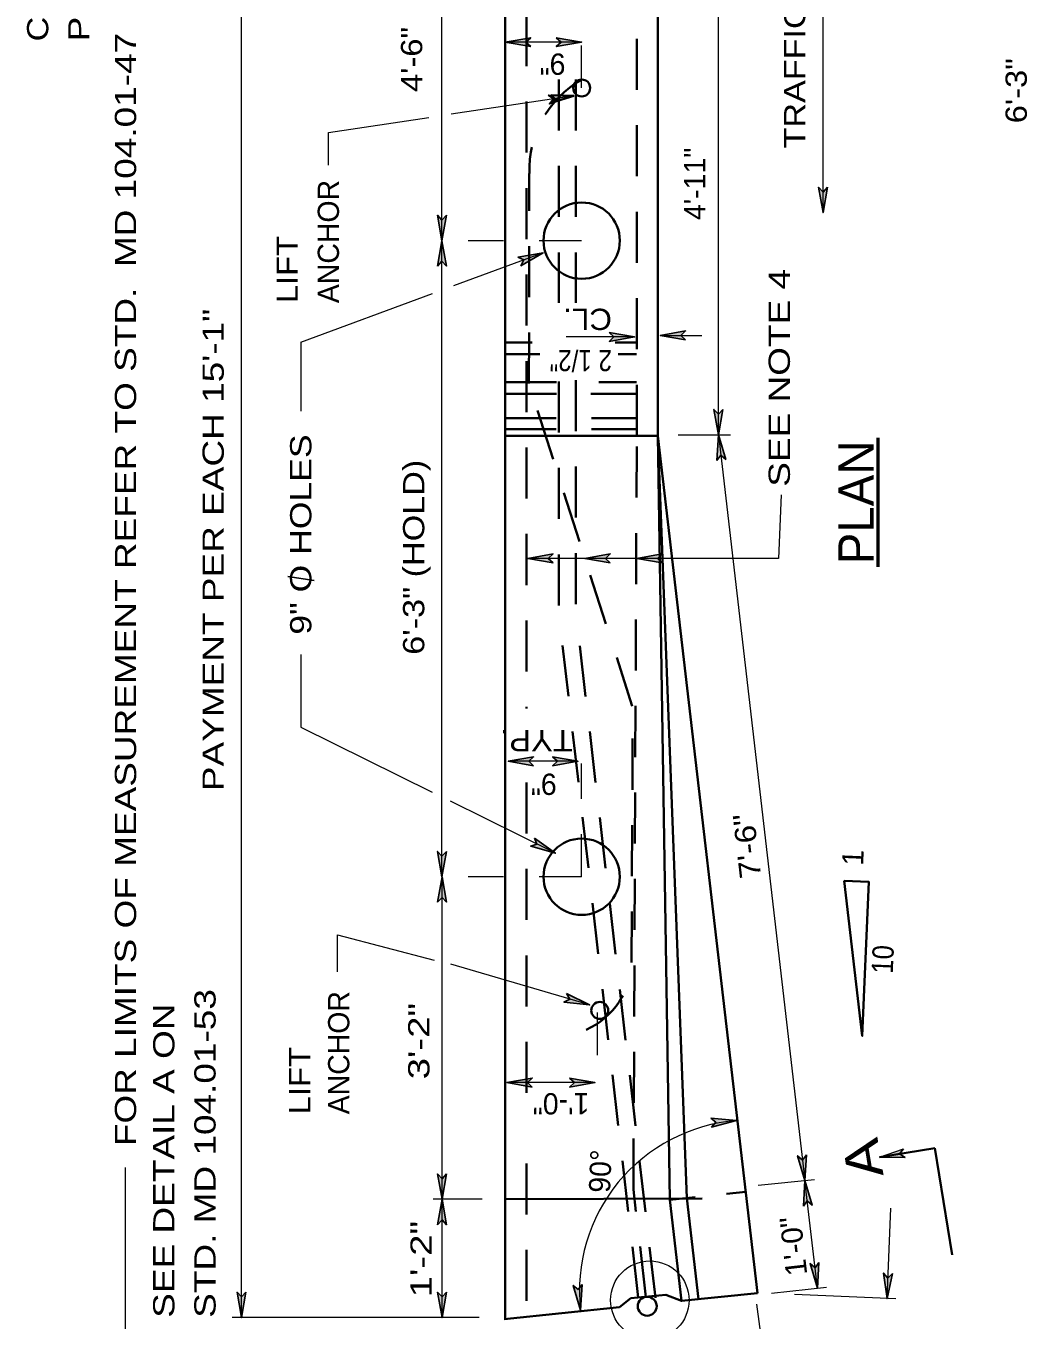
# Model space of a CAD drawing. Extents: x 12.6 to 19.5, y 6.1 to 16.3.
# Drawn here: x 12.689 to 15.514, y 8.696 to 12.348 of the extents above; entities that cross this region are included whole.
import ezdxf
from ezdxf.enums import TextEntityAlignment as Align

# ---------------------------------------------------------------- set-up
doc = ezdxf.new("R2010")
doc.units = 0
doc.header["$LTSCALE"] = 0.024
doc.linetypes.add('DOT_DASHED', pattern=[7.7, 5, -1.2, 0.3, -1.2])
doc.linetypes.add('LONG_DASHED', pattern=[7.5, 6, -1.5])
for name, color, linetype, lineweight in [('1', 7, 'Continuous', 35), ('10', 7, 'Continuous', 25), ('12', 7, 'Continuous', 53)]:
    doc.layers.add(name, color=color, linetype=linetype, lineweight=lineweight)

msp = doc.modelspace()

# ---------------------------------------------------------------- hatches: boundary and pattern name
at = {"layer": '10'}
for points in [[(14.1137, 12.2895), (14.0422, 12.3021), (14.1137, 12.3147), (14.1002, 12.3021)], [(14.186, 12.3147), (14.2575, 12.3021), (14.186, 12.2895), (14.1995, 12.3021)], [(14.1627, 12.1529), (14.2353, 12.1511), (14.1665, 12.128), (14.1779, 12.1425)], [(14.9513, 11.8926), (14.9387, 11.8211), (14.9261, 11.8926), (14.9387, 11.8791)], [(13.8761, 11.8135), (13.8635, 11.742), (13.8509, 11.8135), (13.8635, 11.8)], [(13.8509, 11.6705), (13.8635, 11.742), (13.8761, 11.6705), (13.8635, 11.684)], [(14.0774, 11.6951), (14.1488, 11.708), (14.0861, 11.6714), (14.0944, 11.6879)], [(14.3352, 11.483), (14.4067, 11.4704), (14.3352, 11.4578), (14.3487, 11.4704)], [(14.5506, 11.4621), (14.4791, 11.4747), (14.5506, 11.4873), (14.5371, 11.4747)], [(14.6558, 11.266), (14.6432, 11.1945), (14.6306, 11.266), (14.6432, 11.2525)], [(14.6389, 11.122), (14.6432, 11.1945), (14.664, 11.1249), (14.6499, 11.1369)], [(14.1768, 10.8328), (14.1053, 10.8454), (14.1768, 10.858), (14.1633, 10.8454)], [(14.3383, 10.8328), (14.2668, 10.8454), (14.3383, 10.858), (14.3248, 10.8454)], [(14.4846, 10.8328), (14.4131, 10.8454), (14.4846, 10.858), (14.4711, 10.8454)], [(14.122, 10.2604), (14.0505, 10.273), (14.122, 10.2856), (14.1085, 10.273)], [(14.1755, 10.2856), (14.247, 10.273), (14.1755, 10.2604), (14.189, 10.273)], [(14.1249, 10.0566), (14.1834, 10.0136), (14.1137, 10.034), (14.1314, 10.0393)], [(13.8761, 10.0187), (13.8635, 9.9472), (13.8509, 10.0187), (13.8635, 10.0052)], [(13.851, 9.8757), (13.8636, 9.9472), (13.8762, 9.8757), (13.8636, 9.8892)], [(14.2146, 9.6181), (14.2797, 9.5859), (14.2075, 9.5939), (14.224, 9.6022)], [(14.1182, 9.3539), (14.0467, 9.3665), (14.1182, 9.3791), (14.1047, 9.3665)], [(14.2235, 9.3791), (14.295, 9.3665), (14.2235, 9.3539), (14.237, 9.3665)], [(14.622, 9.266), (14.6943, 9.2592), (14.624, 9.2409), (14.6364, 9.2546)], [(15.1701, 9.155), (15.0975, 9.1559), (15.166, 9.1799), (15.1547, 9.1652)], [(14.8917, 9.1629), (14.8874, 9.0904), (14.8666, 9.16), (14.8807, 9.148)], [(13.8762, 9.1087), (13.8636, 9.0372), (13.851, 9.1087), (13.8636, 9.0952)], [(14.8831, 9.0179), (14.8874, 9.0904), (14.9082, 9.0208), (14.8941, 9.0328)], [(13.851, 8.9657), (13.8636, 9.0372), (13.8762, 8.9657), (13.8636, 8.9792)], [(14.927, 8.8588), (14.9227, 8.7863), (14.9019, 8.8559), (14.916, 8.8439)], [(15.1348, 8.8282), (15.1192, 8.7573), (15.1096, 8.8293), (15.1216, 8.8152)], [(13.3104, 8.7752), (13.2978, 8.7037), (13.2852, 8.7752), (13.2978, 8.7617)], [(13.8762, 8.7752), (13.8636, 8.7037), (13.851, 8.7752), (13.8636, 8.7617)], [(14.2587, 8.7973), (14.2543, 8.7248), (14.2337, 8.7944), (14.2477, 8.7824)]]:
    msp.add_hatch(color=256, dxfattribs=at).paths.add_polyline_path(points)

# ---------------------------------------------------------------- linework, layer by layer
at = {"layer": '1', "linetype": 'LONG_DASHED'}
for p, q in [((14.1021, 12.8664), (14.1021, 10.4224)), ((14.1928, 12.1968), (14.1928, 11.5662)), ((14.2415, 12.1968), (14.2415, 11.5662)), ((14.1087, 11.3386), (14.1099, 11.9313)), ((14.0429, 11.4546), (14.1177, 11.4546)), ((14.4123, 11.4546), (14.3519, 11.4546)), ((14.0429, 11.4222), (14.1399, 11.4222)), ((14.4123, 11.4222), (14.3604, 11.4222)), ((14.0429, 11.3427), (14.1927, 11.3427)), ((14.4003, 10.4286), (14.1087, 11.3386)), ((14.1928, 11.345), (14.1928, 10.6914)), ((14.2415, 11.3485), (14.2415, 10.6912)), ((14.4123, 11.3427), (14.3059, 11.3427)), ((14.0429, 11.3102), (14.2012, 11.3102)), ((14.4123, 11.3102), (14.2838, 11.3102)), ((14.0412, 11.241), (14.4106, 11.241)), ((14.0412, 11.2102), (14.4107, 11.2102)), ((14.4173, 8.7603), (14.1928, 10.6914)), ((14.466, 8.7595), (14.2415, 10.6912)), ((14.398, 9.705), (14.402, 10.4323)), ((14.1021, 9.3376), (14.1021, 10.2412)), ((14.1021, 8.7507), (14.1021, 9.2374))]:
    msp.add_line(p, q, dxfattribs=at)
at = {"layer": '1'}
for p, q in [((14.1714, 12.1521), (14.2353, 12.1511)), ((14.1714, 12.1521), (14.1808, 12.1429)), ((14.1746, 12.1314), (14.2353, 12.1511)), ((14.1746, 12.1314), (14.1808, 12.1429)), ((14.7537, 8.7728), (14.4728, 11.1918)), ((14.5064, 9.036), (14.4728, 11.1918)), ((14.554, 9.0408), (14.4728, 11.1918)), ((14.7207, 9.058), (14.6664, 9.0525)), ((14.5975, 9.0392), (14.0422, 9.0379)), ((14.5064, 9.036), (14.578, 9.0433)), ((14.5872, 8.7556), (14.554, 9.0408)), ((14.4948, 8.7681), (14.3964, 8.7579)), ((14.7537, 8.7728), (14.5395, 8.7507)), ((14.0385, 8.6991), (14.364, 8.7327)), ((14.3964, 8.7579), (14.364, 8.7327))]:
    msp.add_line(p, q, dxfattribs=at)
for points in [[(14.0422, 13.0162), (14.0422, 11.1916), (14.4729, 11.1916), (14.4729, 12.6034)], [(14.0422, 11.1916), (14.0422, 9.0379), (14.0422, 8.7029)], [(14.4948, 8.7681), (14.5395, 8.7507), (14.5064, 9.036)]]:
    msp.add_lwpolyline(points, dxfattribs=at)
at = {"layer": '1', "linetype": 'LONG_DASHED'}
for points in [[(14.4131, 11.1916), (14.4131, 12.6034), (14.3534, 12.8719)], [(14.4391, 8.7607), (14.4036, 9.0652), (14.413, 11.1943)]]:
    msp.add_lwpolyline(points, dxfattribs=at)
at = {"layer": '1'}
for centre, radius in [((14.25762, 12.1728), 0.02393), ((14.25762, 11.74206), 0.10769), ((14.25762, 9.94731), 0.10769), ((14.3085, 9.57006), 0.02393), ((14.44257, 8.73553), 0.02674)]:
    msp.add_circle(centre, radius, dxfattribs=at)
at = {"layer": '1', "linetype": 'LONG_DASHED'}
msp.add_arc((14.40409, 11.94159), 0.29419, 119.85944, 181.98584, dxfattribs=at)
msp.add_ellipse((14.18968, 9.69707), major_axis=(0.19051, 0.08479), ratio=0.952525, start_param=4.712389, end_param=5.9027397, dxfattribs=at)
at = {"layer": '10', "lineweight": 13}
for p, q in [((14.9387, 11.8211), (14.9387, 13.1462)), ((13.2978, 8.7037), (13.2978, 13.0311)), ((14.2575, 12.3021), (14.0422, 12.3021)), ((14.2353, 12.1511), (13.8898, 12.0991)), ((13.5428, 12.0468), (13.8266, 12.0896)), ((13.5428, 11.9551), (13.5428, 12.0468)), ((14.1488, 11.708), (13.8959, 11.6148)), ((13.4649, 11.456), (13.8366, 11.5929)), ((14.4067, 11.4704), (14.2138, 11.4704)), ((14.4791, 11.4747), (14.597, 11.4747)), ((13.4649, 11.456), (13.4649, 11.2607)), ((14.5303, 11.1945), (14.6772, 11.1945)), ((14.6432, 11.1945), (14.8874, 9.0904)), ((14.8201, 11.025), (14.8125, 10.8454)), ((14.2668, 10.8454), (14.1053, 10.8454)), ((13.4649, 10.5746), (13.4649, 10.3698)), ((13.4649, 10.3698), (13.8354, 10.1861)), ((14.247, 10.273), (14.0505, 10.273)), ((14.1834, 10.0136), (13.8873, 10.1603)), ((13.5687, 9.679), (13.5687, 9.7833)), ((13.5687, 9.7833), (13.8414, 9.7118)), ((14.2797, 9.5859), (13.8882, 9.7005)), ((14.295, 9.3665), (14.0467, 9.3665)), ((15.0975, 9.1559), (15.166, 9.1799)), ((15.0975, 9.1559), (15.1701, 9.155)), ((12.9705, 8.2335), (12.9705, 9.1269)), ((14.7555, 9.0768), (14.9146, 9.0932)), ((14.9227, 8.7863), (14.8874, 9.0904)), ((13.9765, 9.0372), (13.8386, 9.0372)), ((15.1192, 8.7573), (15.13, 9.0125)), ((14.793, 8.7729), (14.9484, 8.7889)), ((15.1441, 8.7562), (14.8584, 8.7684)), ((14.7507, 8.7412), (14.8253, 8.1913)), ((13.8537, 8.7037), (13.2719, 8.7037)), ((13.968, 8.7037), (13.8537, 8.7037))]:
    msp.add_line(p, q, dxfattribs=at)
at = {"layer": '10'}
for p, q in [((14.0422, 12.3021), (14.1137, 12.3147)), ((14.2575, 12.3021), (14.186, 12.3147)), ((14.0422, 12.3021), (14.1137, 12.2895)), ((14.2575, 12.3021), (14.186, 12.2895)), ((14.2353, 12.1511), (14.1627, 12.1529)), ((14.2353, 12.1511), (14.1665, 12.128)), ((14.9387, 11.8211), (14.9261, 11.8926)), ((14.9387, 11.8211), (14.9513, 11.8926)), ((13.8635, 11.742), (13.8509, 11.8135)), ((13.8635, 11.742), (13.8761, 11.8135)), ((13.8635, 11.742), (13.8509, 11.6705)), ((13.8635, 11.742), (13.8761, 11.6705)), ((14.1488, 11.708), (14.0774, 11.6951)), ((14.1488, 11.708), (14.0861, 11.6714)), ((14.4067, 11.4704), (14.3352, 11.483)), ((14.4067, 11.4704), (14.3352, 11.4578)), ((14.4791, 11.4747), (14.5506, 11.4873)), ((14.4791, 11.4747), (14.5506, 11.4621)), ((14.6432, 11.1945), (14.6306, 11.266)), ((14.6432, 11.1945), (14.6558, 11.266)), ((14.6432, 11.1945), (14.6389, 11.122)), ((14.6432, 11.1945), (14.664, 11.1249)), ((14.1053, 10.8454), (14.1768, 10.858)), ((14.1053, 10.8454), (14.1768, 10.8328)), ((14.2668, 10.8454), (14.3383, 10.858)), ((14.2668, 10.8454), (14.3383, 10.8328)), ((14.4131, 10.8454), (14.4846, 10.858)), ((14.4131, 10.8454), (14.4846, 10.8328)), ((13.503, 10.7836), (13.4286, 10.7944)), ((14.0505, 10.273), (14.122, 10.2856)), ((14.0505, 10.273), (14.122, 10.2604)), ((14.247, 10.273), (14.1755, 10.2856)), ((14.247, 10.273), (14.1755, 10.2604)), ((14.1834, 10.0136), (14.1249, 10.0566)), ((13.8635, 9.9472), (13.8509, 10.0187)), ((13.8635, 9.9472), (13.8761, 10.0187)), ((14.1834, 10.0136), (14.1137, 10.034)), ((13.8636, 9.9472), (13.851, 9.8757)), ((13.8636, 9.9472), (13.8762, 9.8757)), ((14.2797, 9.5859), (14.2146, 9.6181)), ((14.2797, 9.5859), (14.2075, 9.5939)), ((14.0467, 9.3665), (14.1182, 9.3791)), ((14.0467, 9.3665), (14.1182, 9.3539)), ((14.295, 9.3665), (14.2235, 9.3791)), ((14.295, 9.3665), (14.2235, 9.3539)), ((14.6943, 9.2592), (14.622, 9.266)), ((14.6943, 9.2592), (14.624, 9.2409)), ((14.8874, 9.0904), (14.8666, 9.16)), ((14.8874, 9.0904), (14.8917, 9.1629)), ((13.8636, 9.0372), (13.851, 9.1087)), ((13.8636, 9.0372), (13.8762, 9.1087)), ((14.8874, 9.0904), (14.8831, 9.0179)), ((14.8874, 9.0904), (14.9082, 9.0208)), ((13.8636, 9.0372), (13.851, 8.9657)), ((13.8636, 9.0372), (13.8762, 8.9657)), ((14.9227, 8.7863), (14.9019, 8.8559)), ((14.9227, 8.7863), (14.927, 8.8588)), ((15.1192, 8.7573), (15.1096, 8.8293)), ((15.1192, 8.7573), (15.1348, 8.8282)), ((13.2978, 8.7037), (13.2852, 8.7752)), ((13.2978, 8.7037), (13.3104, 8.7752)), ((13.8636, 8.7037), (13.851, 8.7752)), ((13.8636, 8.7037), (13.8762, 8.7752)), ((14.2543, 8.7248), (14.2337, 8.7944)), ((14.2543, 8.7248), (14.2587, 8.7973))]:
    msp.add_line(p, q, dxfattribs=at)
at = {"layer": '10', "linetype": 'DOT_DASHED', "lineweight": 13}
for p, q in [((14.2575, 12.1728), (14.2575, 12.3271)), ((14.2575, 11.742), (13.8385, 11.742)), ((14.2575, 9.9472), (14.2575, 10.3386)), ((14.2575, 9.9472), (13.8385, 9.9472)), ((14.3016, 9.5643), (14.3016, 9.3451))]:
    msp.add_line(p, q, dxfattribs=at)
at = {"layer": '10', "lineweight": 35}
for p, q in [((15.2543, 9.1815), (15.0975, 9.1559)), ((15.2542, 9.1818), (15.3033, 8.8809))]:
    msp.add_line(p, q, dxfattribs=at)
at = {"layer": '10', "lineweight": 13}
for points in [[(13.8635, 9.9472), (13.8635, 11.742), (13.8635, 13.0311)], [(14.6432, 11.1945), (14.6432, 12.6313), (14.6432, 13.0342)], [(14.8125, 10.8454), (14.4131, 10.8454), (14.2668, 10.8454)], [(13.8636, 8.7037), (13.8636, 9.0372), (13.8636, 9.9472)], [(15.1701, 9.155), (15.1547, 9.1652), (15.166, 9.1799)]]:
    msp.add_lwpolyline(points, dxfattribs=at)
at = {"layer": '10'}
for points in [[(14.1137, 12.2895), (14.0422, 12.3021), (14.1137, 12.3147), (14.1002, 12.3021)], [(14.186, 12.3147), (14.2575, 12.3021), (14.186, 12.2895), (14.1995, 12.3021)], [(14.1627, 12.1529), (14.2353, 12.1511), (14.1665, 12.128), (14.1779, 12.1425)], [(14.9513, 11.8926), (14.9387, 11.8211), (14.9261, 11.8926), (14.9387, 11.8791)], [(13.8761, 11.8135), (13.8635, 11.742), (13.8509, 11.8135), (13.8635, 11.8)], [(13.8509, 11.6705), (13.8635, 11.742), (13.8761, 11.6705), (13.8635, 11.684)], [(14.0774, 11.6951), (14.1488, 11.708), (14.0861, 11.6714), (14.0944, 11.6879)], [(14.3352, 11.483), (14.4067, 11.4704), (14.3352, 11.4578), (14.3487, 11.4704)], [(14.5506, 11.4621), (14.4791, 11.4747), (14.5506, 11.4873), (14.5371, 11.4747)], [(14.6558, 11.266), (14.6432, 11.1945), (14.6306, 11.266), (14.6432, 11.2525)], [(14.6389, 11.122), (14.6432, 11.1945), (14.664, 11.1249), (14.6499, 11.1369)], [(14.1768, 10.8328), (14.1053, 10.8454), (14.1768, 10.858), (14.1633, 10.8454)], [(14.3383, 10.8328), (14.2668, 10.8454), (14.3383, 10.858), (14.3248, 10.8454)], [(14.4846, 10.8328), (14.4131, 10.8454), (14.4846, 10.858), (14.4711, 10.8454)], [(14.122, 10.2604), (14.0505, 10.273), (14.122, 10.2856), (14.1085, 10.273)], [(14.1755, 10.2856), (14.247, 10.273), (14.1755, 10.2604), (14.189, 10.273)], [(14.1249, 10.0566), (14.1834, 10.0136), (14.1137, 10.034), (14.1314, 10.0393)], [(13.8761, 10.0187), (13.8635, 9.9472), (13.8509, 10.0187), (13.8635, 10.0052)], [(13.851, 9.8757), (13.8636, 9.9472), (13.8762, 9.8757), (13.8636, 9.8892)], [(14.2146, 9.6181), (14.2797, 9.5859), (14.2075, 9.5939), (14.224, 9.6022)], [(14.1182, 9.3539), (14.0467, 9.3665), (14.1182, 9.3791), (14.1047, 9.3665)], [(14.2235, 9.3791), (14.295, 9.3665), (14.2235, 9.3539), (14.237, 9.3665)], [(14.622, 9.266), (14.6943, 9.2592), (14.624, 9.2409), (14.6364, 9.2546)], [(14.8917, 9.1629), (14.8874, 9.0904), (14.8666, 9.16), (14.8807, 9.148)], [(13.8762, 9.1087), (13.8636, 9.0372), (13.851, 9.1087), (13.8636, 9.0952)], [(14.8831, 9.0179), (14.8874, 9.0904), (14.9082, 9.0208), (14.8941, 9.0328)], [(13.851, 8.9657), (13.8636, 9.0372), (13.8762, 8.9657), (13.8636, 8.9792)], [(14.927, 8.8588), (14.9227, 8.7863), (14.9019, 8.8559), (14.916, 8.8439)], [(15.1348, 8.8282), (15.1192, 8.7573), (15.1096, 8.8293), (15.1216, 8.8152)], [(13.3104, 8.7752), (13.2978, 8.7037), (13.2852, 8.7752), (13.2978, 8.7617)], [(13.8762, 8.7752), (13.8636, 8.7037), (13.851, 8.7752), (13.8636, 8.7617)], [(14.2587, 8.7973), (14.2543, 8.7248), (14.2337, 8.7944), (14.2477, 8.7824)]]:
    msp.add_lwpolyline(points, close=True, dxfattribs=at)
for points in [[(14.1137, 12.2895), (14.1002, 12.3021), (14.1137, 12.3147)], [(14.186, 12.3147), (14.1995, 12.3021), (14.186, 12.2895)], [(14.1627, 12.1529), (14.1779, 12.1425), (14.1665, 12.128)], [(14.9513, 11.8926), (14.9387, 11.8791), (14.9261, 11.8926)], [(13.8761, 11.8135), (13.8635, 11.8), (13.8509, 11.8135)], [(14.0774, 11.6951), (14.0944, 11.6879), (14.0861, 11.6714)], [(13.8509, 11.6705), (13.8635, 11.684), (13.8761, 11.6705)], [(14.3352, 11.483), (14.3487, 11.4704), (14.3352, 11.4578)], [(14.5506, 11.4621), (14.5371, 11.4747), (14.5506, 11.4873)], [(14.6558, 11.266), (14.6432, 11.2525), (14.6306, 11.266)], [(14.6389, 11.122), (14.6499, 11.1369), (14.664, 11.1249)], [(14.1768, 10.8328), (14.1633, 10.8454), (14.1768, 10.858)], [(14.3383, 10.8328), (14.3248, 10.8454), (14.3383, 10.858)], [(14.4846, 10.8328), (14.4711, 10.8454), (14.4846, 10.858)], [(14.122, 10.2604), (14.1085, 10.273), (14.122, 10.2856)], [(14.1755, 10.2856), (14.189, 10.273), (14.1755, 10.2604)], [(14.1249, 10.0566), (14.1314, 10.0393), (14.1137, 10.034)], [(13.8761, 10.0187), (13.8635, 10.0052), (13.8509, 10.0187)], [(13.851, 9.8757), (13.8636, 9.8892), (13.8762, 9.8757)], [(14.2146, 9.6181), (14.224, 9.6022), (14.2075, 9.5939)], [(14.1182, 9.3539), (14.1047, 9.3665), (14.1182, 9.3791)], [(14.2235, 9.3791), (14.237, 9.3665), (14.2235, 9.3539)], [(14.622, 9.266), (14.6364, 9.2546), (14.624, 9.2409)], [(14.8917, 9.1629), (14.8807, 9.148), (14.8666, 9.16)], [(13.8762, 9.1087), (13.8636, 9.0952), (13.851, 9.1087)], [(14.8831, 9.0179), (14.8941, 9.0328), (14.9082, 9.0208)], [(13.851, 8.9657), (13.8636, 8.9792), (13.8762, 8.9657)], [(14.927, 8.8588), (14.916, 8.8439), (14.9019, 8.8559)], [(15.1348, 8.8282), (15.1216, 8.8152), (15.1096, 8.8293)], [(13.3104, 8.7752), (13.2978, 8.7617), (13.2852, 8.7752)], [(13.8762, 8.7752), (13.8636, 8.7617), (13.851, 8.7752)], [(14.2587, 8.7973), (14.2477, 8.7824), (14.2337, 8.7944)]]:
    msp.add_lwpolyline(points, dxfattribs=at)
at = {"layer": '10', "lineweight": 35}
msp.add_lwpolyline([(14.9984, 9.9362), (15.0492, 9.4984), (15.0676, 9.9333)], close=True, dxfattribs=at)
at = {"layer": '10', "lineweight": 13}
msp.add_lwpolyline([(15.1701, 9.155), (15.0975, 9.1559), (15.166, 9.1799), (15.1547, 9.1652)], close=True, dxfattribs=at)
msp.add_circle((14.44991, 8.75269), 0.11072, dxfattribs=at)
msp.add_arc((14.73288, 8.77907), 0.48169, 94.60034, 186.46968, dxfattribs=at)
at = {"layer": '12'}
msp.add_line((15.0945, 10.8218), (15.0945, 11.1855), dxfattribs=at)

# ---------------------------------------------------------------- texts
for s, height, rotation, width, p in [('CONNECTOR LOOPS (RECEIVE THE CONNECTOR', 0.06, 90, 1.2, (12.7526, 12.3042)), ('PIN) SEE STD. MD 104.01-54 FOR DETAILS', 0.06, 90, 1.3, (12.8688, 12.3042)), ('4\'-6"', 0.06, 90, 1.15, (13.8077, 12.1614)), ('6\'-3"', 0.06, 90, 1.15, (15.5136, 12.0732)), ('LIFT', 0.06, 90, 1.15, (13.4566, 11.5657)), ('SEE NOTE 4', 0.06, 90, 1.3, (14.8451, 11.0477)), ('CL.', 0.06, 180, 1.1, (14.3431, 11.55)), ('2 1/2"', 0.06, 180, 0.85, (14.3431, 11.4338)), ('TYP.', 0.06, 180, 1.15, (14.2327, 10.3611)), ('7\'-6"', 0.06, 96.624, 1.15, (14.7643, 9.9461)), ('10', 0.06, 87.58, 0.9, (15.1353, 9.6729)), ('STD. MD 104.01-53', 0.06, 90, 1.3, (13.2247, 8.7029)), ('SEE DETAIL A ON', 0.06, 90, 1.3, (13.1085, 8.7029)), ('3\'-2"', 0.06, 90, 1.35, (13.8281, 9.3757)), ('LIFT', 0.06, 90, 1.15, (13.492, 9.2771)), ('A', 0.1, 99.255, 1.25, (15.1095, 9.1049)), ('1\'-2"', 0.06, 90, 1.35, (13.8346, 8.7607)), ('1\'-0"', 0.06, 96.626, 1.05, (14.8943, 8.825))]:
    msp.add_text(s, height=height, rotation=rotation, dxfattribs=dict(at, width=width)).set_placement(p)
for s, width, p in [('TRAFFIC DIRECTION', 1.2, (14.8887, 12.4836)), ('FOR LIMITS OF MEASUREMENT REFER TO STD.  MD 104.01-47', 1.3, (13.0005, 10.75775)), ('PAYMENT PER EACH 15\'-1"', 1.3, (13.2478, 10.8694)), ('9" O HOLES', 1.25, (13.4949, 10.9129)), ('6\'-3" (HOLD)', 1.2, (13.8135, 10.8487))]:
    msp.add_text(s, height=0.06, rotation=90, dxfattribs=dict(at, width=width)).set_placement(p, align=Align.CENTER)
for s, rotation, p in [('9"', 180, (14.212, 12.27)), ('4\'-11"', 90, (14.6063, 11.8001)), ('ANCHOR', 90, (13.5728, 11.5657)), ('9"', 180, (14.1873, 10.2382)), ('1', 87.58, (15.0517, 9.9778)), ('ANCHOR', 90, (13.602, 9.2771)), ('1\'-0"', 180, (14.2792, 9.3368)), ('90°', 87.58, (14.3375, 9.0547))]:
    msp.add_text(s, height=0.06, rotation=rotation, dxfattribs=at).set_placement(p)
msp.add_text('PLAN', height=0.1, rotation=90, dxfattribs=at).set_placement((15.0819, 11.00365), align=Align.CENTER)

doc.saveas('drawing.dxf')
